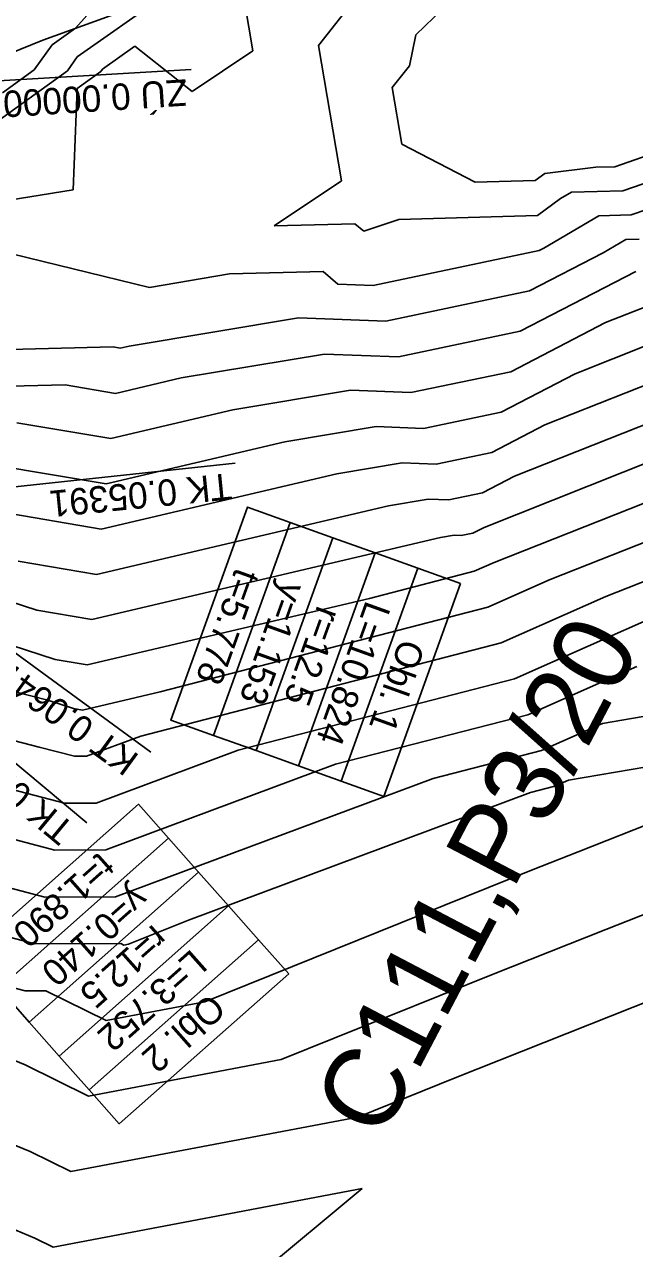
# Model space of a CAD drawing. Extents: x -549394 to -546608, y -1037055 to -1033629.
# Drawn here: x -547816 to -547735.2, y -1035700.8 to -1035538.5 of the extents above; entities that cross this region are included whole.
import ezdxf

# ---------------------------------------------------------------- set-up
doc = ezdxf.new("R2010")
doc.units = 0
for name, color, linetype in [('hlavni_vrst', 7, 'Continuous'), ('hrana_L', 7, 'Continuous'), ('norm_vrst', 7, 'Continuous'), ('x_popis_C111', 7, 'Continuous'), ('x_popis_oblouky_C111', 7, 'Continuous')]:
    doc.layers.add(name, color=color, linetype=linetype)

msp = doc.modelspace()

# ---------------------------------------------------------------- linework, layer by layer
at = {"layer": 'hlavni_vrst'}
for p, q in [((-547777.04, -1035541.33), (-547769.48, -1035531.68)), ((-547774.03, -1035559.28), (-547777.04, -1035541.33)), ((-547718.39, -1035554.17), (-547736.73, -1035560.59)), ((-547782.94, -1035565.21), (-547774.03, -1035559.28)), ((-547743.54, -1035560.76), (-547744.99, -1035561.61)), ((-547736.73, -1035560.59), (-547743.54, -1035560.76)), ((-547744.99, -1035561.61), (-547748.04, -1035563.85)), ((-547766.41, -1035564.39), (-547771.06, -1035565.95)), ((-547748.04, -1035563.85), (-547766.41, -1035564.39)), ((-547772.23, -1035564.94), (-547782.94, -1035565.21)), ((-547771.06, -1035565.95), (-547772.23, -1035564.94)), ((-547733.09, -1035580.87), (-547743.07, -1035584.83)), ((-547743.07, -1035584.83), (-547752.85, -1035589.91)), ((-547752.85, -1035589.91), (-547763.14, -1035592.07)), ((-547769.4, -1035591.83), (-547781.52, -1035593.85)), ((-547763.14, -1035592.07), (-547769.4, -1035591.83)), ((-547781.52, -1035593.85), (-547805.21, -1035599.43)), ((-547805.21, -1035599.43), (-547821.72, -1035596.64)), ((-547731.51, -1035606.21), (-547746.38, -1035612.11)), ((-547746.38, -1035612.11), (-547754.65, -1035615.77)), ((-547754.65, -1035615.77), (-547798.04, -1035626.99)), ((-547812.93, -1035628.1), (-547830.53, -1035623.58)), ((-547798.04, -1035626.99), (-547808.34, -1035629.41)), ((-547809.51, -1035629.21), (-547812.93, -1035628.1)), ((-547808.34, -1035629.41), (-547809.51, -1035629.21)), ((-547719.52, -1035634.57), (-547743.94, -1035638.7)), ((-547743.94, -1035638.7), (-547745.77, -1035639.51)), ((-547748.99, -1035640.35), (-547794.29, -1035657.24)), ((-547745.77, -1035639.51), (-547748.99, -1035640.35)), ((-547814.63, -1035660.41), (-547849.55, -1035651.2)), ((-547794.29, -1035657.24), (-547802.23, -1035660.44)), ((-547803.24, -1035660.37), (-547814.63, -1035660.41)), ((-547802.86, -1035660.56), (-547803.24, -1035660.37)), ((-547802.23, -1035660.44), (-547802.86, -1035660.56))]:
    msp.add_line(p, q, dxfattribs=at)
at = {"layer": 'hrana_L'}
for p, q in [((-547813.58, -1035540.62), (-547792.07, -1035532.74)), ((-547832.01, -1035548.06), (-547813.58, -1035540.62))]:
    msp.add_line(p, q, dxfattribs=at)
at = {"layer": 'norm_vrst'}
for p, q in [((-547809.23, -1035539.03), (-547805.82, -1035535.12)), ((-547809.01, -1035542.84), (-547797.48, -1035534.72)), ((-547785.74, -1035542.05), (-547786.8, -1035535.75)), ((-547764.16, -1035539.9), (-547759.4, -1035535.33)), ((-547812.35, -1035541.22), (-547809.23, -1035539.03)), ((-547765, -1035544.01), (-547764.16, -1035539.9)), ((-547814.73, -1035544.55), (-547812.35, -1035541.22)), ((-547805.68, -1035544.47), (-547801.37, -1035541.43)), ((-547801.37, -1035541.43), (-547793.79, -1035547.41)), ((-547810.32, -1035544.67), (-547809.01, -1035542.84)), ((-547793.79, -1035547.41), (-547785.74, -1035542.05)), ((-547821.28, -1035552.58), (-547810.32, -1035544.67)), ((-547818.92, -1035547.58), (-547814.73, -1035544.55)), ((-547809.01, -1035547.02), (-547805.91, -1035544.79)), ((-547805.91, -1035544.79), (-547805.68, -1035544.47)), ((-547767.28, -1035546.91), (-547765, -1035544.01)), ((-547809.54, -1035560.47), (-547809.01, -1035547.02)), ((-547766.02, -1035554.41), (-547767.28, -1035546.91)), ((-547756.31, -1035559.46), (-547766.02, -1035554.41)), ((-547729.27, -1035554.41), (-547737.81, -1035557.4)), ((-547740.3, -1035557.46), (-547747.06, -1035558.29)), ((-547737.81, -1035557.4), (-547740.3, -1035557.46)), ((-547748.34, -1035559.23), (-547756.31, -1035559.46)), ((-547747.06, -1035558.29), (-547748.34, -1035559.23)), ((-547824.52, -1035562.85), (-547809.54, -1035560.47)), ((-547724.11, -1035559.75), (-547735.65, -1035563.79)), ((-547739.94, -1035563.89), (-547747.21, -1035568.18)), ((-547735.65, -1035563.79), (-547739.94, -1035563.89)), ((-547736.34, -1035567.03), (-547739.33, -1035568.79)), ((-547734.57, -1035566.98), (-547736.34, -1035567.03)), ((-547799.43, -1035573.39), (-547821.16, -1035568.08)), ((-547747.85, -1035568.51), (-547769.8, -1035573.12)), ((-547739.33, -1035568.79), (-547749.1, -1035573.86)), ((-547747.21, -1035568.18), (-547747.85, -1035568.51)), ((-547788.87, -1035571.59), (-547799.43, -1035573.39)), ((-547776.43, -1035571.27), (-547788.87, -1035571.59)), ((-547774.49, -1035572.94), (-547776.43, -1035571.27)), ((-547735.03, -1035571.26), (-547750.35, -1035579.21)), ((-547769.8, -1035573.12), (-547774.49, -1035572.94)), ((-547749.1, -1035573.86), (-547768.14, -1035577.86)), ((-547733.41, -1035575.81), (-547739.05, -1035578.04)), ((-547779.72, -1035577.42), (-547802.13, -1035581.16)), ((-547768.14, -1035577.86), (-547779.72, -1035577.42)), ((-547739.05, -1035578.04), (-547751.6, -1035584.56)), ((-547750.35, -1035579.21), (-547766.47, -1035582.59)), ((-547804.25, -1035581.28), (-547834.2, -1035582)), ((-547803.33, -1035581.44), (-547804.25, -1035581.28)), ((-547802.13, -1035581.16), (-547803.33, -1035581.44)), ((-547776.28, -1035582.22), (-547795.26, -1035585.39)), ((-547766.47, -1035582.59), (-547776.28, -1035582.22)), ((-547795.26, -1035585.39), (-547803.96, -1035587.44)), ((-547751.6, -1035584.56), (-547764.81, -1035587.33)), ((-547810.63, -1035586.31), (-547829.92, -1035586.77)), ((-547803.96, -1035587.44), (-547810.63, -1035586.31)), ((-547772.84, -1035587.03), (-547788.39, -1035589.62)), ((-547764.81, -1035587.33), (-547772.84, -1035587.03)), ((-547732.77, -1035585.94), (-547747.09, -1035591.62)), ((-547788.39, -1035589.62), (-547804.58, -1035593.43)), ((-547804.58, -1035593.43), (-547817.01, -1035591.33)), ((-547747.09, -1035591.62), (-547754.1, -1035595.26)), ((-547732.46, -1035591.01), (-547751.11, -1035598.41)), ((-547754.1, -1035595.26), (-547761.47, -1035596.8)), ((-547765.96, -1035596.63), (-547774.64, -1035598.08)), ((-547761.47, -1035596.8), (-547765.96, -1035596.63)), ((-547732.14, -1035596.08), (-547755.13, -1035605.19)), ((-547774.64, -1035598.08), (-547805.84, -1035605.43)), ((-547751.11, -1035598.41), (-547755.35, -1035600.61)), ((-547762.52, -1035601.44), (-547767.77, -1035602.32)), ((-547759.81, -1035601.54), (-547762.52, -1035601.44)), ((-547755.35, -1035600.61), (-547759.81, -1035601.54)), ((-547731.82, -1035601.14), (-547753.78, -1035609.85)), ((-547805.84, -1035605.43), (-547819.27, -1035603.15)), ((-547767.77, -1035602.32), (-547806.46, -1035611.42)), ((-547760.9, -1035606.55), (-547807.09, -1035617.42)), ((-547759.08, -1035606.24), (-547760.9, -1035606.55)), ((-547758.14, -1035606.28), (-547759.08, -1035606.24)), ((-547756.6, -1035605.96), (-547758.14, -1035606.28)), ((-547755.13, -1035605.19), (-547756.6, -1035605.96)), ((-547806.46, -1035611.42), (-547816.83, -1035609.67)), ((-547753.78, -1035609.85), (-547756.42, -1035611.02)), ((-547756.42, -1035611.02), (-547770.3, -1035614.61)), ((-547731.19, -1035611.28), (-547738.98, -1035614.37)), ((-547814.39, -1035616.18), (-547824.89, -1035612.77)), ((-547770.3, -1035614.61), (-547807.72, -1035623.41)), ((-547738.98, -1035614.37), (-547752.87, -1035620.52)), ((-547807.09, -1035617.42), (-547814.39, -1035616.18)), ((-547731.58, -1035616.62), (-547751.1, -1035625.27)), ((-547811.95, -1035622.7), (-547824.38, -1035618.66)), ((-547752.87, -1035620.52), (-547800.58, -1035632.85)), ((-547807.72, -1035623.41), (-547811.95, -1035622.7)), ((-547734.91, -1035623.63), (-547749.32, -1035630.02)), ((-547751.1, -1035625.27), (-547787.68, -1035634.73)), ((-547814.08, -1035634.31), (-547834.93, -1035628.95)), ((-547723.42, -1035628.46), (-547739.42, -1035631.17)), ((-547749.32, -1035630.02), (-547774.79, -1035636.6)), ((-547739.42, -1035631.17), (-547747.54, -1035634.76)), ((-547800.58, -1035632.85), (-547807.79, -1035635.54)), ((-547809.39, -1035635.54), (-547814.08, -1035634.31)), ((-547807.79, -1035635.54), (-547809.39, -1035635.54)), ((-547787.68, -1035634.73), (-547806.51, -1035641.75)), ((-547747.54, -1035634.76), (-547761.89, -1035638.47)), ((-547774.79, -1035636.6), (-547805.23, -1035647.95)), ((-547810.7, -1035641.76), (-547822.95, -1035638.53)), ((-547761.89, -1035638.47), (-547803.95, -1035654.16)), ((-547806.51, -1035641.75), (-547810.7, -1035641.76)), ((-547812.01, -1035647.98), (-547831.81, -1035642.75)), ((-547729.59, -1035643.04), (-547742.66, -1035648.19)), ((-547813.32, -1035654.2), (-547840.68, -1035646.98)), ((-547805.23, -1035647.95), (-547812.01, -1035647.98)), ((-547742.66, -1035648.19), (-547748.84, -1035650.65)), ((-547715.03, -1035649.03), (-547739.01, -1035658.48)), ((-547748.84, -1035650.65), (-547792.11, -1035668.08)), ((-547803.95, -1035654.16), (-547813.32, -1035654.2)), ((-547739.01, -1035658.48), (-547753.9, -1035664.41)), ((-547815.94, -1035666.63), (-547835.62, -1035661.44)), ((-547753.9, -1035664.41), (-547781.99, -1035675.72)), ((-547725.57, -1035664.91), (-547735.36, -1035668.77)), ((-547813.18, -1035666.62), (-547815.94, -1035666.63)), ((-547805.2, -1035670.56), (-547813.18, -1035666.62)), ((-547792.11, -1035668.08), (-547805.2, -1035670.56)), ((-547735.36, -1035668.77), (-547758.96, -1035678.16)), ((-547815.92, -1035676.43), (-547824.21, -1035673.02)), ((-547807.54, -1035680.57), (-547815.92, -1035676.43)), ((-547781.99, -1035675.72), (-547807.54, -1035680.57)), ((-547815.27, -1035687.91), (-547835.75, -1035679.5)), ((-547758.96, -1035678.16), (-547771.86, -1035683.36)), ((-547771.86, -1035683.36), (-547809.88, -1035690.57)), ((-547814.62, -1035699.39), (-547847.29, -1035685.97)), ((-547809.88, -1035690.57), (-547815.27, -1035687.91)), ((-547771.29, -1035692.81), (-547812.23, -1035700.58)), ((-547797.3, -1035714.51), (-547771.29, -1035692.81)), ((-547812.23, -1035700.58), (-547814.62, -1035699.39))]:
    msp.add_line(p, q, dxfattribs=at)
at = {"layer": 'x_popis_oblouky_C111'}
for points in [[(-547835.24, -1035546.95), (-547793.94, -1035544.51)], [(-547828.42, -1035601.02), (-547788.09, -1035596.68)], [(-547832.14, -1035610.96), (-547799.25, -1035634.97)], [(-547839, -1035618.25), (-547807.76, -1035644.36)]]:
    msp.add_lwpolyline(points, dxfattribs=at)
for points in [[(-547780.83, -1035604.53), (-547790.98, -1035632.76), (-547796.63, -1035630.73), (-547786.48, -1035602.5)], [(-547775.18, -1035606.56), (-547785.33, -1035634.79), (-547790.98, -1035632.76), (-547780.83, -1035604.53)], [(-547769.54, -1035608.59), (-547779.69, -1035636.82), (-547785.33, -1035634.79), (-547775.18, -1035606.56)], [(-547763.89, -1035610.62), (-547774.04, -1035638.85), (-547779.69, -1035636.82), (-547769.54, -1035608.59)], [(-547758.24, -1035612.65), (-547768.4, -1035640.88), (-547774.04, -1035638.85), (-547763.89, -1035610.62)], [(-547796.93, -1035646.39), (-547819.38, -1035666.29), (-547823.36, -1035661.8), (-547800.91, -1035641.9)], [(-547792.95, -1035650.88), (-547815.4, -1035670.78), (-547819.38, -1035666.29), (-547796.93, -1035646.39)], [(-547788.97, -1035655.37), (-547811.42, -1035675.27), (-547815.4, -1035670.78), (-547792.95, -1035650.88)], [(-547784.99, -1035659.86), (-547807.44, -1035679.76), (-547811.42, -1035675.27), (-547788.97, -1035655.37)], [(-547781.01, -1035664.35), (-547803.46, -1035684.25), (-547807.44, -1035679.76), (-547784.99, -1035659.86)]]:
    msp.add_lwpolyline(points, close=True, dxfattribs=at)

# ---------------------------------------------------------------- texts
at = {"layer": 'x_popis_C111'}
msp.add_text('C111,P3/20', height=10.5, rotation=62.3301, dxfattribs=at).set_placement((-547768.73, -1035686.58))
at = {"layer": 'x_popis_oblouky_C111'}
for s, rotation, p in [('ZÚ 0.00000', 183.7076, (-547794.54, -1035545.79)), ('TK 0.05391', 185.6624, (-547788.75, -1035597.99)), ('t=5.778', 250.2443, (-547788.03, -1035610.39)), ('y=1.153', 250.2443, (-547781.9, -1035612.1)), ('r=12.5', 250.2443, (-547777.18, -1035615.41)), ('L=10.824', 250.2443, (-547770.75, -1035614.75)), ('Obl. 1', 250.2443, (-547766.19, -1035619.8)), ('KT 0.06474', 144.0374, (-547800.65, -1035635.48)), ('TK 0.07474', 140.3303, (-547809.16, -1035644.8)), ('t=1.890', 221.5842, (-547806.06, -1035648.08)), ('y=0.140', 221.5842, (-547801.5, -1035652.52)), ('r=12.5', 221.5842, (-547798.95, -1035657.69)), ('L=3.752', 221.5842, (-547793.86, -1035660.96)), ('Obl. 2', 221.5842, (-547791.4, -1035666.81))]:
    msp.add_text(s, height=3.5, rotation=rotation, dxfattribs=at).set_placement(p)

doc.saveas('drawing.dxf')
